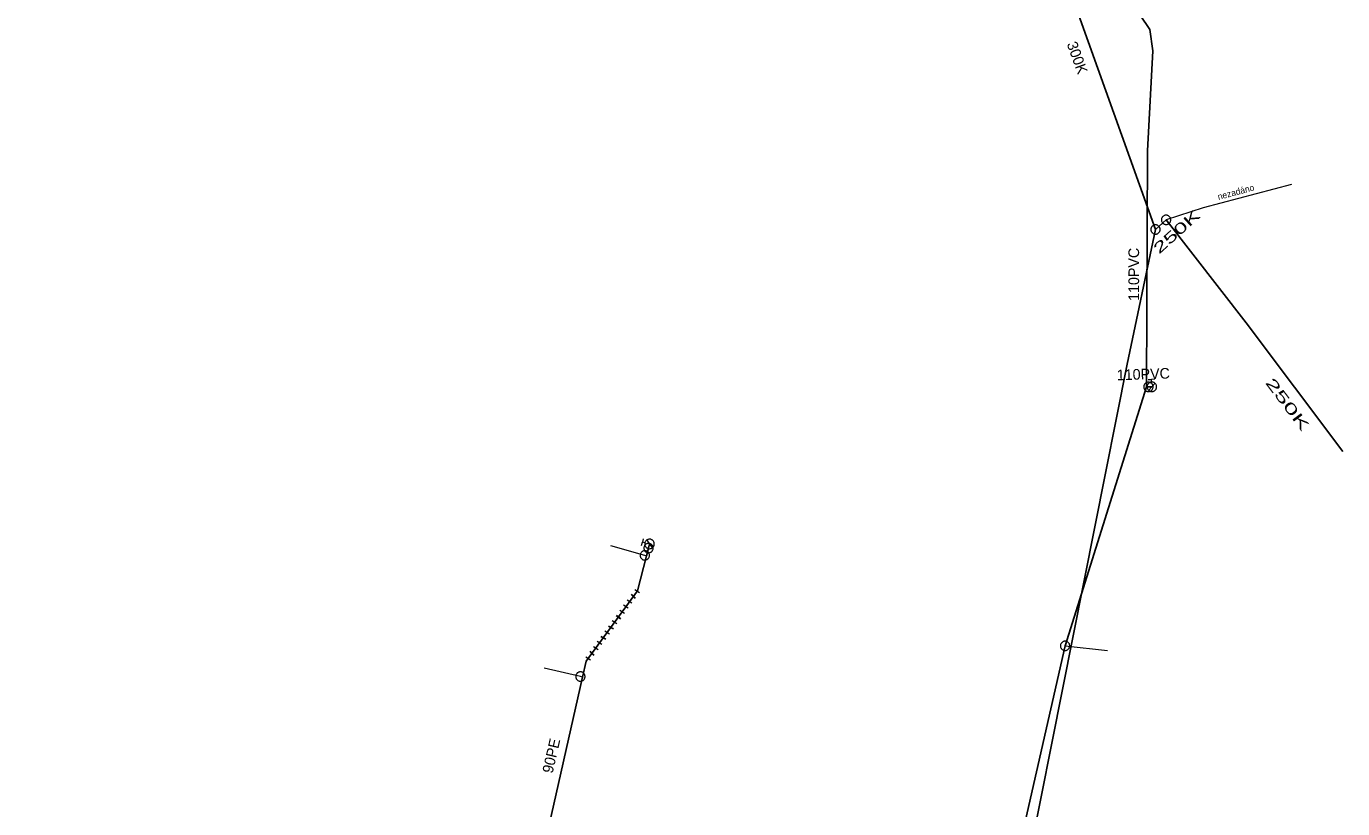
# Model space of a CAD drawing. Extents: x -741806 to -738704, y -1059275 to -1055387.
# Drawn here: x -740595 to -740471.5, y -1057719.6 to -1057646.1 of the extents above; entities that cross this region are included whole.
import ezdxf

# ---------------------------------------------------------------- set-up
doc = ezdxf.new("R2010")
doc.units = 0
doc.header["$LTSCALE"] = 0.4
doc.linetypes.add('DOTTED', pattern=[1.5, 0.3, -1.2])
for name, color, linetype, lineweight in [('2', 7, 'Continuous', 25), ('21', 7, 'Continuous', 13), ('3', 7, 'Continuous', 13), ('31', 7, 'DOTTED', 140), ('50', 7, 'Continuous', 13), ('51', 7, 'Continuous', 13), ('52', 7, 'Continuous', 25), ('56', 7, 'Continuous', 13)]:
    doc.layers.add(name, color=color, linetype=linetype, lineweight=lineweight)
for name, color, linetype in [('5', 7, 'Continuous'), ('53', 7, 'Continuous'), ('55', 7, 'Continuous')]:
    doc.layers.add(name, color=color, linetype=linetype)

msp = doc.modelspace()

# ---------------------------------------------------------------- linework, layer by layer
at = {"layer": '2'}
for p, q in [((-740489.039, -1057665.21), (-740500.629, -1057632.81)), ((-740488.039, -1057664.31), (-740489.039, -1057665.21))]:
    msp.add_line(p, q, dxfattribs=at)
for points in [[(-740471.467, -1057686.044), (-740480.53, -1057673.96), (-740488.039, -1057664.31)], [(-740609.006, -1057979.487), (-740608.671, -1057978.605), (-740585.671, -1057978.608), (-740567.046, -1057933.639), (-740552.184, -1057895.72), (-740535.835, -1057854.115), (-740530.462, -1057837.318), (-740525.059, -1057820.845), (-740524.232, -1057813.604), (-740512.355, -1057767.872), (-740507.212, -1057752.35), (-740500.784, -1057723.652), (-740491.688, -1057677.854), (-740489.039, -1057665.21)]]:
    msp.add_lwpolyline(points, dxfattribs=at)
at = {"layer": '21'}
msp.add_line((-740497.519, -1057704.287), (-740493.543, -1057704.74), dxfattribs=at)
for points in [[(-740536.809, -1057695.83), (-740536.96, -1057695.8), (-740540.16, -1057694.899)], [(-740542.809, -1057707.24), (-740543.01, -1057707.169), (-740546.399, -1057706.389)]]:
    msp.add_lwpolyline(points, dxfattribs=at)
at = {"layer": '3'}
for points in [[(-740488.455, -1057664.445), (-740488.438, -1057664.487), (-740488.417, -1057664.528), (-740488.392, -1057664.567), (-740488.364, -1057664.602), (-740488.331, -1057664.634), (-740488.295, -1057664.663), (-740488.257, -1057664.688), (-740488.216, -1057664.709), (-740488.173, -1057664.724), (-740488.129, -1057664.736), (-740488.084, -1057664.744), (-740488.037, -1057664.746), (-740487.992, -1057664.743), (-740487.947, -1057664.737), (-740487.903, -1057664.724), (-740487.86, -1057664.708), (-740487.819, -1057664.686), (-740487.781, -1057664.662), (-740487.745, -1057664.633), (-740487.713, -1057664.6), (-740487.685, -1057664.564), (-740487.66, -1057664.527), (-740487.639, -1057664.485), (-740487.622, -1057664.443), (-740487.611, -1057664.398), (-740487.604, -1057664.353), (-740487.601, -1057664.308), (-740487.604, -1057664.261), (-740487.611, -1057664.216), (-740487.624, -1057664.172), (-740487.64, -1057664.13), (-740487.66, -1057664.089), (-740487.686, -1057664.05), (-740487.715, -1057664.015), (-740487.747, -1057663.983), (-740487.783, -1057663.954), (-740487.821, -1057663.929), (-740487.863, -1057663.908), (-740487.905, -1057663.893), (-740487.949, -1057663.881), (-740487.994, -1057663.873), (-740488.04, -1057663.871), (-740488.086, -1057663.873), (-740488.131, -1057663.88), (-740488.175, -1057663.893), (-740488.218, -1057663.909), (-740488.259, -1057663.93), (-740488.297, -1057663.955), (-740488.332, -1057663.984), (-740488.365, -1057664.017), (-740488.393, -1057664.053), (-740488.419, -1057664.09), (-740488.439, -1057664.132), (-740488.455, -1057664.174), (-740488.467, -1057664.219), (-740488.474, -1057664.264), (-740488.476, -1057664.309), (-740488.474, -1057664.356), (-740488.466, -1057664.401), (-740488.455, -1057664.444)], [(-740488.948, -1057664.781), (-740488.993, -1057664.775), (-740489.038, -1057664.772), (-740489.085, -1057664.775), (-740489.129, -1057664.782), (-740489.174, -1057664.794), (-740489.217, -1057664.81), (-740489.257, -1057664.832), (-740489.296, -1057664.856), (-740489.331, -1057664.886), (-740489.363, -1057664.918), (-740489.392, -1057664.954), (-740489.418, -1057664.992), (-740489.437, -1057665.033), (-740489.454, -1057665.075), (-740489.466, -1057665.12), (-740489.473, -1057665.165), (-740489.475, -1057665.211), (-740489.473, -1057665.256), (-740489.465, -1057665.302), (-740489.453, -1057665.346), (-740489.436, -1057665.389), (-740489.416, -1057665.429), (-740489.39, -1057665.468), (-740489.362, -1057665.503), (-740489.329, -1057665.536), (-740489.293, -1057665.564), (-740489.255, -1057665.589), (-740489.214, -1057665.61), (-740489.171, -1057665.626), (-740489.127, -1057665.638), (-740489.082, -1057665.645), (-740489.037, -1057665.647), (-740488.99, -1057665.645), (-740488.945, -1057665.637), (-740488.901, -1057665.625), (-740488.858, -1057665.609), (-740488.818, -1057665.588), (-740488.779, -1057665.562), (-740488.744, -1057665.534), (-740488.712, -1057665.502), (-740488.683, -1057665.466), (-740488.658, -1057665.427), (-740488.637, -1057665.387), (-740488.621, -1057665.344), (-740488.609, -1057665.299), (-740488.602, -1057665.254), (-740488.599, -1057665.208), (-740488.602, -1057665.163), (-740488.61, -1057665.117), (-740488.622, -1057665.073), (-740488.639, -1057665.031), (-740488.659, -1057664.99), (-740488.685, -1057664.952), (-740488.713, -1057664.916), (-740488.746, -1057664.884), (-740488.782, -1057664.855), (-740488.82, -1057664.83), (-740488.861, -1057664.809), (-740488.904, -1057664.793), (-740488.947, -1057664.781)]]:
    msp.add_lwpolyline(points, dxfattribs=at)
at = {"layer": '31'}
msp.add_line((-740537.649, -1057699.12), (-740542.46, -1057705.74), dxfattribs=at)
at = {"layer": '50'}
for p, q in [((-740489.707, -1057679.29), (-740489.4, -1057679.277)), ((-740489.093, -1057679.264), (-740489.4, -1057679.277)), ((-740489.389, -1057679.527), (-740489.4, -1057679.277)), ((-740489.369, -1057679.974), (-740489.673, -1057680.304)), ((-740489.369, -1057679.974), (-740489.068, -1057679.649)), ((-740537.266, -1057694.856), (-740537.194, -1057694.556)), ((-740537.121, -1057694.258), (-740537.194, -1057694.556)), ((-740536.95, -1057694.616), (-740537.194, -1057694.556)), ((-740536.515, -1057694.721), (-740536.744, -1057694.341)), ((-740536.515, -1057694.721), (-740536.282, -1057695.104))]:
    msp.add_line(p, q, dxfattribs=at)
for points in [[(-740488.926, -1057679.959), (-740488.931, -1057679.91), (-740488.938, -1057679.865), (-740488.952, -1057679.819), (-740488.971, -1057679.777), (-740488.992, -1057679.738), (-740489.021, -1057679.698), (-740489.051, -1057679.664), (-740489.085, -1057679.631), (-740489.122, -1057679.602), (-740489.163, -1057679.58), (-740489.205, -1057679.56), (-740489.248, -1057679.543), (-740489.295, -1057679.534), (-740489.341, -1057679.528), (-740489.387, -1057679.527), (-740489.433, -1057679.532), (-740489.478, -1057679.539), (-740489.523, -1057679.554), (-740489.566, -1057679.573), (-740489.608, -1057679.596), (-740489.645, -1057679.622), (-740489.681, -1057679.653), (-740489.713, -1057679.687), (-740489.74, -1057679.723), (-740489.765, -1057679.764), (-740489.786, -1057679.806), (-740489.8, -1057679.85), (-740489.812, -1057679.897), (-740489.815, -1057679.943), (-740489.819, -1057679.989), (-740489.814, -1057680.037), (-740489.804, -1057680.082), (-740489.791, -1057680.125), (-740489.773, -1057680.17), (-740489.75, -1057680.21), (-740489.724, -1057680.249), (-740489.693, -1057680.283), (-740489.659, -1057680.316), (-740489.62, -1057680.345), (-740489.581, -1057680.367), (-740489.537, -1057680.387), (-740489.493, -1057680.402), (-740489.45, -1057680.414), (-740489.401, -1057680.42), (-740489.355, -1057680.421), (-740489.309, -1057680.416), (-740489.263, -1057680.406), (-740489.218, -1057680.393), (-740489.175, -1057680.375), (-740489.133, -1057680.351), (-740489.096, -1057680.326), (-740489.06, -1057680.294), (-740489.029, -1057680.261), (-740489, -1057680.225), (-740488.978, -1057680.183), (-740488.956, -1057680.142), (-740488.941, -1057680.097), (-740488.933, -1057680.052), (-740488.927, -1057680.005)], [(-740536.406, -1057694.29), (-740536.454, -1057694.281), (-740536.5, -1057694.275), (-740536.548, -1057694.277), (-740536.594, -1057694.283), (-740536.637, -1057694.292), (-740536.683, -1057694.309), (-740536.724, -1057694.329), (-740536.766, -1057694.353), (-740536.804, -1057694.38), (-740536.836, -1057694.413), (-740536.867, -1057694.447), (-740536.896, -1057694.485), (-740536.917, -1057694.527), (-740536.935, -1057694.57), (-740536.949, -1057694.614), (-740536.957, -1057694.659), (-740536.963, -1057694.704), (-740536.961, -1057694.752), (-740536.955, -1057694.799), (-740536.945, -1057694.845), (-740536.93, -1057694.888), (-740536.91, -1057694.931), (-740536.886, -1057694.971), (-740536.859, -1057695.007), (-740536.826, -1057695.043), (-740536.792, -1057695.074), (-740536.754, -1057695.1), (-740536.712, -1057695.124), (-740536.669, -1057695.14), (-740536.626, -1057695.157), (-740536.578, -1057695.165), (-740536.532, -1057695.168), (-740536.487, -1057695.168), (-740536.439, -1057695.163), (-740536.394, -1057695.152), (-740536.349, -1057695.138), (-740536.308, -1057695.117), (-740536.266, -1057695.094), (-740536.228, -1057695.064), (-740536.196, -1057695.033), (-740536.164, -1057694.996), (-740536.139, -1057694.958), (-740536.115, -1057694.92), (-740536.096, -1057694.874), (-740536.082, -1057694.83), (-740536.074, -1057694.785), (-740536.071, -1057694.738), (-740536.07, -1057694.691), (-740536.076, -1057694.645), (-740536.087, -1057694.598), (-740536.101, -1057694.556), (-740536.122, -1057694.512), (-740536.145, -1057694.473), (-740536.172, -1057694.436), (-740536.206, -1057694.403), (-740536.239, -1057694.37), (-740536.278, -1057694.343), (-740536.319, -1057694.323), (-740536.362, -1057694.304)]]:
    msp.add_lwpolyline(points, close=True, dxfattribs=at)
at = {"layer": '51'}
for points in [[(-740489.259, -1057679.965), (-740489.263, -1057679.92), (-740489.272, -1057679.875), (-740489.286, -1057679.831), (-740489.303, -1057679.789), (-740489.326, -1057679.749), (-740489.353, -1057679.711), (-740489.383, -1057679.678), (-740489.416, -1057679.646), (-740489.454, -1057679.62), (-740489.493, -1057679.596), (-740489.534, -1057679.577), (-740489.578, -1057679.562), (-740489.623, -1057679.552), (-740489.668, -1057679.546), (-740489.714, -1057679.546), (-740489.76, -1057679.55), (-740489.804, -1057679.559), (-740489.848, -1057679.573), (-740489.89, -1057679.592), (-740489.93, -1057679.615), (-740489.967, -1057679.641), (-740490.002, -1057679.671), (-740490.032, -1057679.705), (-740490.06, -1057679.741), (-740490.083, -1057679.781), (-740490.103, -1057679.823), (-740490.117, -1057679.866), (-740490.127, -1057679.911), (-740490.132, -1057679.956), (-740490.133, -1057680.002), (-740490.128, -1057680.047), (-740490.119, -1057680.092), (-740490.105, -1057680.136), (-740490.088, -1057680.178), (-740490.065, -1057680.218), (-740490.038, -1057680.256), (-740490.008, -1057680.289), (-740489.975, -1057680.321), (-740489.937, -1057680.347), (-740489.898, -1057680.371), (-740489.857, -1057680.39), (-740489.813, -1057680.405), (-740489.768, -1057680.414), (-740489.723, -1057680.421), (-740489.677, -1057680.421), (-740489.631, -1057680.417), (-740489.587, -1057680.407), (-740489.543, -1057680.394), (-740489.501, -1057680.375), (-740489.461, -1057680.352), (-740489.424, -1057680.326), (-740489.389, -1057680.296), (-740489.358, -1057680.262), (-740489.331, -1057680.226), (-740489.308, -1057680.186), (-740489.288, -1057680.144), (-740489.274, -1057680.101), (-740489.264, -1057680.056), (-740489.259, -1057680.011), (-740489.259, -1057679.966)], [(-740537.388, -1057695.713), (-740537.395, -1057695.758), (-740537.397, -1057695.803), (-740537.394, -1057695.85), (-740537.386, -1057695.894), (-740537.374, -1057695.938), (-740537.357, -1057695.982), (-740537.335, -1057696.022), (-740537.31, -1057696.06), (-740537.281, -1057696.095), (-740537.248, -1057696.127), (-740537.212, -1057696.155), (-740537.173, -1057696.18), (-740537.133, -1057696.201), (-740537.09, -1057696.217), (-740537.045, -1057696.228), (-740537, -1057696.235), (-740536.954, -1057696.237), (-740536.909, -1057696.233), (-740536.863, -1057696.225), (-740536.819, -1057696.213), (-740536.777, -1057696.196), (-740536.736, -1057696.175), (-740536.698, -1057696.149), (-740536.663, -1057696.12), (-740536.631, -1057696.087), (-740536.602, -1057696.051), (-740536.578, -1057696.013), (-740536.557, -1057695.971), (-740536.542, -1057695.928), (-740536.53, -1057695.884), (-740536.524, -1057695.839), (-740536.522, -1057695.794), (-740536.525, -1057695.747), (-740536.532, -1057695.703), (-740536.545, -1057695.659), (-740536.562, -1057695.615), (-740536.583, -1057695.575), (-740536.608, -1057695.537), (-740536.638, -1057695.502), (-740536.67, -1057695.47), (-740536.706, -1057695.442), (-740536.745, -1057695.417), (-740536.786, -1057695.397), (-740536.829, -1057695.38), (-740536.874, -1057695.37), (-740536.919, -1057695.362), (-740536.965, -1057695.361), (-740537.01, -1057695.364), (-740537.055, -1057695.372), (-740537.1, -1057695.384), (-740537.142, -1057695.401), (-740537.183, -1057695.422), (-740537.221, -1057695.448), (-740537.256, -1057695.477), (-740537.288, -1057695.51), (-740537.317, -1057695.546), (-740537.341, -1057695.584), (-740537.361, -1057695.626), (-740537.377, -1057695.669), (-740537.388, -1057695.712)], [(-740536.501, -1057694.692), (-740536.545, -1057694.682), (-740536.59, -1057694.677), (-740536.637, -1057694.677), (-740536.681, -1057694.681), (-740536.726, -1057694.691), (-740536.77, -1057694.705), (-740536.812, -1057694.724), (-740536.852, -1057694.746), (-740536.889, -1057694.773), (-740536.923, -1057694.803), (-740536.954, -1057694.837), (-740536.981, -1057694.875), (-740537.004, -1057694.914), (-740537.023, -1057694.955), (-740537.037, -1057694.999), (-740537.047, -1057695.044), (-740537.052, -1057695.09), (-740537.052, -1057695.135), (-740537.047, -1057695.181), (-740537.037, -1057695.226), (-740537.023, -1057695.269), (-740537.005, -1057695.311), (-740536.982, -1057695.351), (-740536.956, -1057695.388), (-740536.925, -1057695.422), (-740536.89, -1057695.453), (-740536.854, -1057695.48), (-740536.814, -1057695.503), (-740536.772, -1057695.522), (-740536.729, -1057695.537), (-740536.684, -1057695.546), (-740536.639, -1057695.551), (-740536.593, -1057695.551), (-740536.548, -1057695.546), (-740536.503, -1057695.537), (-740536.459, -1057695.523), (-740536.417, -1057695.504), (-740536.377, -1057695.482), (-740536.341, -1057695.454), (-740536.306, -1057695.424), (-740536.275, -1057695.39), (-740536.248, -1057695.353), (-740536.226, -1057695.313), (-740536.206, -1057695.272), (-740536.192, -1057695.228), (-740536.182, -1057695.183), (-740536.178, -1057695.138), (-740536.177, -1057695.092), (-740536.182, -1057695.046), (-740536.192, -1057695.001), (-740536.206, -1057694.958), (-740536.224, -1057694.916), (-740536.247, -1057694.877), (-740536.273, -1057694.839), (-740536.305, -1057694.805), (-740536.339, -1057694.774), (-740536.375, -1057694.748), (-740536.415, -1057694.724), (-740536.457, -1057694.706), (-740536.5, -1057694.692)], [(-740497.084, -1057704.336), (-740497.081, -1057704.292), (-740497.083, -1057704.246), (-740497.09, -1057704.2), (-740497.101, -1057704.156), (-740497.117, -1057704.113), (-740497.138, -1057704.072), (-740497.163, -1057704.034), (-740497.191, -1057703.997), (-740497.223, -1057703.965), (-740497.258, -1057703.936), (-740497.297, -1057703.911), (-740497.337, -1057703.889), (-740497.38, -1057703.872), (-740497.424, -1057703.86), (-740497.469, -1057703.853), (-740497.515, -1057703.85), (-740497.561, -1057703.851), (-740497.606, -1057703.858), (-740497.65, -1057703.87), (-740497.693, -1057703.887), (-740497.734, -1057703.907), (-740497.773, -1057703.931), (-740497.808, -1057703.96), (-740497.841, -1057703.992), (-740497.87, -1057704.027), (-740497.896, -1057704.066), (-740497.917, -1057704.106), (-740497.934, -1057704.149), (-740497.946, -1057704.193), (-740497.954, -1057704.238), (-740497.956, -1057704.283), (-740497.954, -1057704.329), (-740497.947, -1057704.375), (-740497.936, -1057704.419), (-740497.92, -1057704.462), (-740497.899, -1057704.503), (-740497.875, -1057704.541), (-740497.847, -1057704.578), (-740497.814, -1057704.61), (-740497.779, -1057704.639), (-740497.741, -1057704.664), (-740497.7, -1057704.686), (-740497.657, -1057704.702), (-740497.614, -1057704.715), (-740497.568, -1057704.722), (-740497.522, -1057704.725), (-740497.477, -1057704.723), (-740497.432, -1057704.717), (-740497.387, -1057704.705), (-740497.344, -1057704.688), (-740497.303, -1057704.668), (-740497.264, -1057704.644), (-740497.229, -1057704.615), (-740497.196, -1057704.583), (-740497.167, -1057704.547), (-740497.141, -1057704.509), (-740497.121, -1057704.469), (-740497.104, -1057704.426), (-740497.092, -1057704.382), (-740497.084, -1057704.337)], [(-740543.422, -1057707.024), (-740543.435, -1057707.067), (-740543.443, -1057707.112), (-740543.447, -1057707.158), (-740543.445, -1057707.203), (-740543.439, -1057707.249), (-740543.428, -1057707.294), (-740543.413, -1057707.336), (-740543.393, -1057707.378), (-740543.369, -1057707.416), (-740543.341, -1057707.452), (-740543.309, -1057707.486), (-740543.274, -1057707.516), (-740543.237, -1057707.542), (-740543.196, -1057707.563), (-740543.154, -1057707.58), (-740543.11, -1057707.594), (-740543.065, -1057707.602), (-740543.019, -1057707.605), (-740542.973, -1057707.603), (-740542.928, -1057707.597), (-740542.883, -1057707.586), (-740542.84, -1057707.572), (-740542.799, -1057707.551), (-740542.76, -1057707.528), (-740542.724, -1057707.499), (-740542.69, -1057707.467), (-740542.661, -1057707.433), (-740542.635, -1057707.394), (-740542.614, -1057707.354), (-740542.596, -1057707.312), (-740542.584, -1057707.268), (-740542.575, -1057707.224), (-740542.572, -1057707.177), (-740542.573, -1057707.132), (-740542.579, -1057707.087), (-740542.59, -1057707.041), (-740542.606, -1057706.999), (-740542.625, -1057706.957), (-740542.65, -1057706.919), (-740542.677, -1057706.883), (-740542.709, -1057706.849), (-740542.744, -1057706.819), (-740542.782, -1057706.794), (-740542.822, -1057706.772), (-740542.865, -1057706.755), (-740542.909, -1057706.741), (-740542.954, -1057706.734), (-740542.999, -1057706.73), (-740543.045, -1057706.732), (-740543.091, -1057706.738), (-740543.135, -1057706.749), (-740543.178, -1057706.764), (-740543.219, -1057706.784), (-740543.258, -1057706.808), (-740543.295, -1057706.836), (-740543.328, -1057706.868), (-740543.357, -1057706.902), (-740543.383, -1057706.941), (-740543.405, -1057706.981), (-740543.421, -1057707.023)]]:
    msp.add_lwpolyline(points, dxfattribs=at)
at = {"layer": '52'}
msp.add_line((-740489.868, -1057679.99), (-740489.37, -1057679.97), dxfattribs=at)
for points in [[(-740503.249, -1057612.745), (-740497.41, -1057632.81), (-740494.239, -1057639.129), (-740493.326, -1057640.857), (-740489.55, -1057646.45), (-740489.27, -1057648.429), (-740489.789, -1057657.84), (-740489.868, -1057679.99)], [(-740489.868, -1057679.99), (-740497.519, -1057704.287), (-740502.89, -1057727.946), (-740504.09, -1057731.52), (-740504.16, -1057731.78), (-740504.295, -1057732.394), (-740505.458, -1057737.884), (-740512.487, -1057766.415), (-740507.033, -1057770.061), (-740517.328, -1057816.22), (-740521.664, -1057829.6), (-740544.85, -1057893.509), (-740554.399, -1057919.446), (-740570.451, -1057950.712), (-740592.697, -1058007.398), (-740600.714, -1058010.487), (-740613.05, -1058039.97), (-740626.485, -1058069.3)], [(-740546.449, -1057723.31), (-740546.39, -1057723.04), (-740542.809, -1057707.24), (-740542.46, -1057705.74), (-740537.649, -1057699.12), (-740536.809, -1057695.83), (-740536.616, -1057695.114), (-740536.52, -1057694.72)]]:
    msp.add_lwpolyline(points, dxfattribs=at)
at = {"layer": '56'}
msp.add_lwpolyline([(-740476.276, -1057660.977), (-740484.559, -1057663.169), (-740488.039, -1057664.31)], dxfattribs=at)

# ---------------------------------------------------------------- texts
at = {"layer": '5'}
msp.add_text('300K', height=1, rotation=290, dxfattribs=at).set_placement((-740497.377, -1057647.795))
for rotation, width, p in [(42, 1.7, (-740488.698, -1057667.573)), (307, 1.85, (-740478.785, -1057679.592))]:
    msp.add_text('250K', height=1, rotation=rotation, dxfattribs=dict(at, width=width)).set_placement(p)
at = {"layer": '53'}
for s, rotation, p in [('110PVC', 90, (-740490.574, -1057671.912)), ('110PVC', 2, (-740492.647, -1057679.371)), ('90PE', 77, (-740545.623, -1057716.31))]:
    msp.add_text(s, height=1, rotation=rotation, dxfattribs=at).set_placement(p)
at = {"layer": '55'}
msp.add_text('nezadáno  ', height=0.6, rotation=15, dxfattribs=at).set_placement((-740483.112, -1057662.444))

doc.saveas('drawing.dxf')
